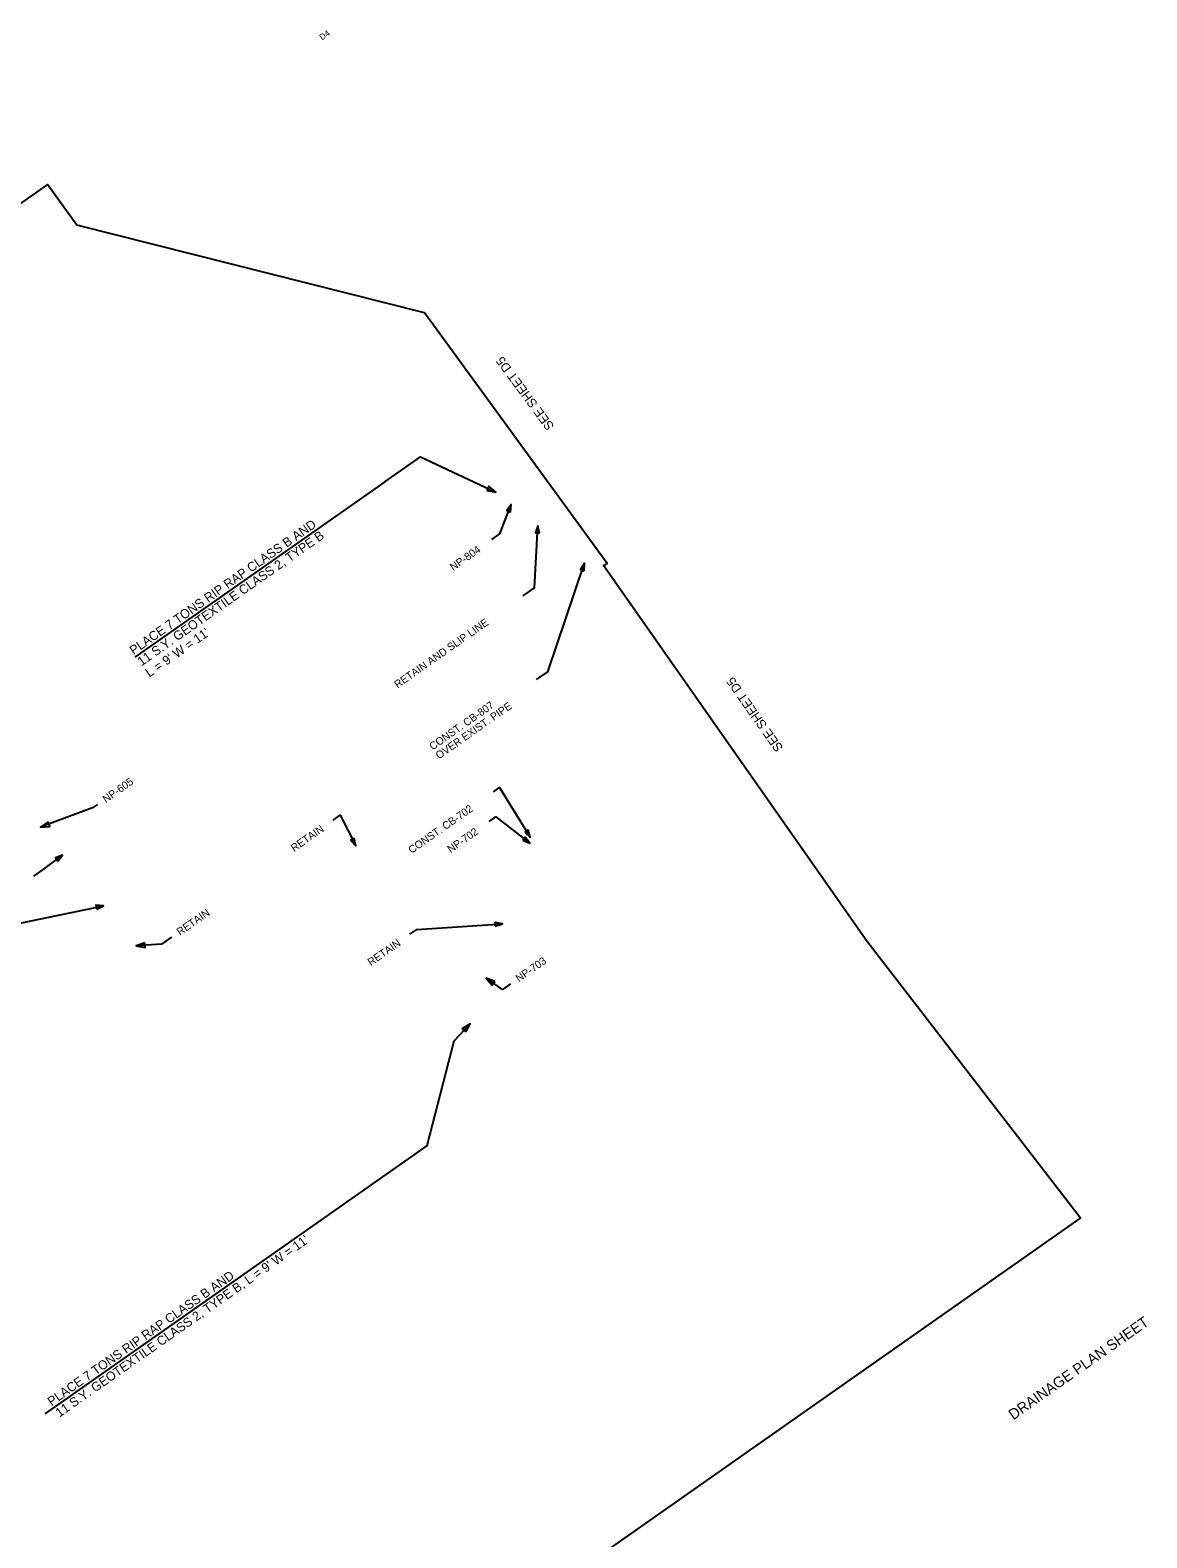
# Model space of a CAD drawing. Extents: x 1605516 to 1608098, y 1090174 to 1092111.
# Drawn here: x 1607365 to 1608098, y 1091123 to 1092111 of the extents above; entities that cross this region are included whole.
import ezdxf

# ---------------------------------------------------------------- set-up
doc = ezdxf.new("R2010")
doc.units = 0
for name, color, linetype in [('Level 13', 7, 'Continuous'), ('RD_HC_CL-reloc', 7, 'Continuous'), ('RD_HC_Data_Tic', 7, 'Continuous'), ('RD_PD_ALT1_TrvlWay', 7, 'Continuous'), ('RD_TX_PEShield', 7, 'Continuous')]:
    doc.layers.add(name, color=color, linetype=linetype)

msp = doc.modelspace()

# ---------------------------------------------------------------- linework, layer by layer
at = {"layer": 'RD_HC_CL-reloc'}
msp.add_lwpolyline([(1606406.67, 1091049.1), (1606535.89, 1090871.82), (1606533.04, 1090870.54), (1606692.25, 1090643.55), (1606817.56, 1090464.9), (1608054.17, 1091332.29), (1607913.93, 1091513.97), (1607741.11, 1091760.35), (1607743.52, 1091761.59), (1607623.71, 1091925.97), (1607395.62, 1091983.59), (1607376.3, 1092010.18), (1606278.89, 1091240.8)], close=True, dxfattribs=at)
msp.add_lwpolyline([(1606406.67, 1091049.1), (1606535.89, 1090871.82), (1606533.04, 1090870.54), (1606692.25, 1090643.55), (1606817.56, 1090464.9), (1608054.17, 1091332.29), (1607913.93, 1091513.97), (1607741.11, 1091760.35), (1607743.52, 1091761.59), (1607623.71, 1091925.97), (1607395.62, 1091983.59), (1607376.3, 1092010.18), (1606278.89, 1091240.8)], close=True, dxfattribs=at)
msp.add_lwpolyline([(1606406.67, 1091049.1), (1606535.89, 1090871.82), (1606533.04, 1090870.54), (1606692.25, 1090643.55), (1606817.56, 1090464.9), (1608054.17, 1091332.29), (1607913.93, 1091513.97), (1607741.11, 1091760.35), (1607743.52, 1091761.59), (1607623.71, 1091925.97), (1607395.62, 1091983.59), (1607376.3, 1092010.18), (1606278.89, 1091240.8)], close=True, dxfattribs=at)
msp.add_lwpolyline([(1606406.67, 1091049.1), (1606535.89, 1090871.82), (1606533.04, 1090870.54), (1606692.25, 1090643.55), (1606817.56, 1090464.9), (1608054.17, 1091332.29), (1607913.93, 1091513.97), (1607741.11, 1091760.35), (1607743.52, 1091761.59), (1607623.71, 1091925.97), (1607395.62, 1091983.59), (1607376.3, 1092010.18), (1606278.89, 1091240.8)], close=True, dxfattribs=at)
msp.add_lwpolyline([(1606406.67, 1091049.1), (1606535.89, 1090871.82), (1606533.04, 1090870.54), (1606692.25, 1090643.55), (1606817.56, 1090464.9), (1608054.17, 1091332.29), (1607913.93, 1091513.97), (1607741.11, 1091760.35), (1607743.52, 1091761.59), (1607623.71, 1091925.97), (1607395.62, 1091983.59), (1607376.3, 1092010.18), (1606278.89, 1091240.8)], close=True, dxfattribs=at)
msp.add_lwpolyline([(1606406.67, 1091049.1), (1606535.89, 1090871.82), (1606533.04, 1090870.54), (1606692.25, 1090643.55), (1606817.56, 1090464.9), (1608054.17, 1091332.29), (1607913.93, 1091513.97), (1607741.11, 1091760.35), (1607743.52, 1091761.59), (1607623.71, 1091925.97), (1607395.62, 1091983.59), (1607376.3, 1092010.18), (1606278.89, 1091240.8)], close=True, dxfattribs=at)
at = {"layer": 'RD_PD_ALT1_TrvlWay'}
for p, q in [((1607597.59, 1091815.22), (1607433.67, 1091700.25)), ((1607625.53, 1091379.93), (1607374.54, 1091203.88))]:
    msp.add_line(p, q, dxfattribs=at)
for points in [[(1607597.59, 1091815.22), (1607620.98, 1091831.63), (1607670.53, 1091808.45)], [(1607667.9, 1091777.44), (1607673.04, 1091781.05), (1607680.68, 1091800.32)], [(1607688.39, 1091740.41), (1607695.9, 1091745.68), (1607698.06, 1091786.41)], [(1607697.24, 1091685.45), (1607704.64, 1091690.63), (1607728.76, 1091761.84)], [(1607669.07, 1091611.89), (1607672.95, 1091614.62), (1607693.13, 1091582.05)], [(1607409.07, 1091603.6), (1607405.81, 1091601.31), (1607371.8, 1091588.65)], [(1607563.7, 1091593.31), (1607568.28, 1091596.53), (1607578.56, 1091576.43)], [(1607666.2, 1091592.44), (1607670.52, 1091595.48), (1607692.76, 1091578.23)], [(1607367.36, 1091556.63), (1607373.12, 1091560.67), (1607386.13, 1091570.38)], [(1607296.88, 1091511.99), (1607298.9, 1091513.4), (1607413.08, 1091537.21)], [(1607614.1, 1091518.44), (1607618.67, 1091521.65), (1607674.92, 1091525.31)], [(1607457.72, 1091516.57), (1607451.2, 1091512), (1607434.46, 1091510.97)], [(1607680.16, 1091486.04), (1607674.84, 1091482.31), (1607664.25, 1091489.59)], [(1607625.53, 1091379.93), (1607643.11, 1091448.54), (1607653.57, 1091459.65)]]:
    msp.add_lwpolyline(points, dxfattribs=at)
for points in [[(1607664.62, 1091809.5), (1607670.53, 1091808.45), (1607665.94, 1091812.31)], [(1607680.1, 1091795.36), (1607680.68, 1091800.32), (1607677.69, 1091796.31)], [(1607699.1, 1091781.52), (1607698.06, 1091786.41), (1607696.51, 1091781.65)], [(1607728.43, 1091756.85), (1607728.76, 1091761.84), (1607725.98, 1091757.68)], [(1607376.69, 1091592.13), (1607371.8, 1091588.65), (1607377.77, 1091589.22)], [(1607575.21, 1091580.14), (1607578.56, 1091576.43), (1607577.51, 1091581.32)], [(1607688.15, 1091580.17), (1607692.76, 1091578.23), (1607689.74, 1091582.21)], [(1607689.48, 1091585.47), (1607693.13, 1091582.05), (1607691.68, 1091586.83)], [(1607383.04, 1091566.46), (1607386.13, 1091570.38), (1607381.49, 1091568.53)], [(1607408.61, 1091534.96), (1607413.08, 1091537.21), (1607408.08, 1091537.49)], [(1607670.19, 1091523.7), (1607674.92, 1091525.31), (1607670.02, 1091526.28)], [(1607440.15, 1091512.87), (1607434.46, 1091510.97), (1607440.34, 1091509.77)], [(1607669.9, 1091487.59), (1607664.25, 1091489.59), (1607668.14, 1091485.03)], [(1607650.73, 1091454.37), (1607653.57, 1091459.65), (1607648.47, 1091456.49)]]:
    msp.add_lwpolyline(points, close=True, dxfattribs=at)

# ---------------------------------------------------------------- texts
at = {"layer": 'Level 13'}
msp.add_text('DRAINAGE PLAN SHEET', height=6.9833, rotation=35.04683, dxfattribs=at).set_placement((1608010.13, 1091199.66))
at = {"layer": 'RD_HC_Data_Tic'}
for rotation, p in [(126.38123, (1607709.12, 1091851.76)), (125.0981, (1607859.35, 1091640.75))]:
    msp.add_text('SEE SHEET D5', height=6, rotation=rotation, dxfattribs=at).set_placement(p)
at = {"layer": 'RD_PD_ALT1_TrvlWay'}
for s, height, p in [('PLACE 7 TONS RIP RAP CLASS B AND', 6, (1607432.81, 1091701.48)), ('11 S.Y. GEOTEXTILE CLASS 2, TYPE B', 6, (1607437.98, 1091694.11)), ('NP-804', 5, (1607642.55, 1091756.6)), ("L = 9' W = 11'", 6, (1607443.14, 1091686.74)), ('RETAIN AND SLIP LINE', 5, (1607606.02, 1091679.59)), ('CONST. CB-807', 5, (1607629.05, 1091638.96)), ('OVER EXIST. PIPE', 5, (1607633.19, 1091633.06)), ('NP-605', 5, (1607414.6, 1091604.43)), ('CONST. CB-702', 5, (1607615.3, 1091571.12)), ('RETAIN', 5, (1607538.15, 1091572.34)), ('NP-702', 5, (1607640.85, 1091571.61)), ('RETAIN', 5, (1607463.25, 1091517.4)), ('RETAIN', 5, (1607588.55, 1091497.47)), ('NP-703', 5, (1607685.69, 1091486.87)), ("11 S.Y. GEOTEXTILE CLASS 2, TYPE B, L = 9' W = 11'", 6, (1607384.13, 1091201.44)), ('PLACE 7 TONS RIP RAP CLASS B AND', 6, (1607378.96, 1091208.81))]:
    msp.add_text(s, height=height, rotation=35.04683, dxfattribs=at).set_placement(p)
at = {"layer": 'RD_TX_PEShield'}
msp.add_text('D4', height=4, rotation=35.04683, dxfattribs=at).set_placement((1607556.47, 1092104.59))

doc.saveas('drawing.dxf')
